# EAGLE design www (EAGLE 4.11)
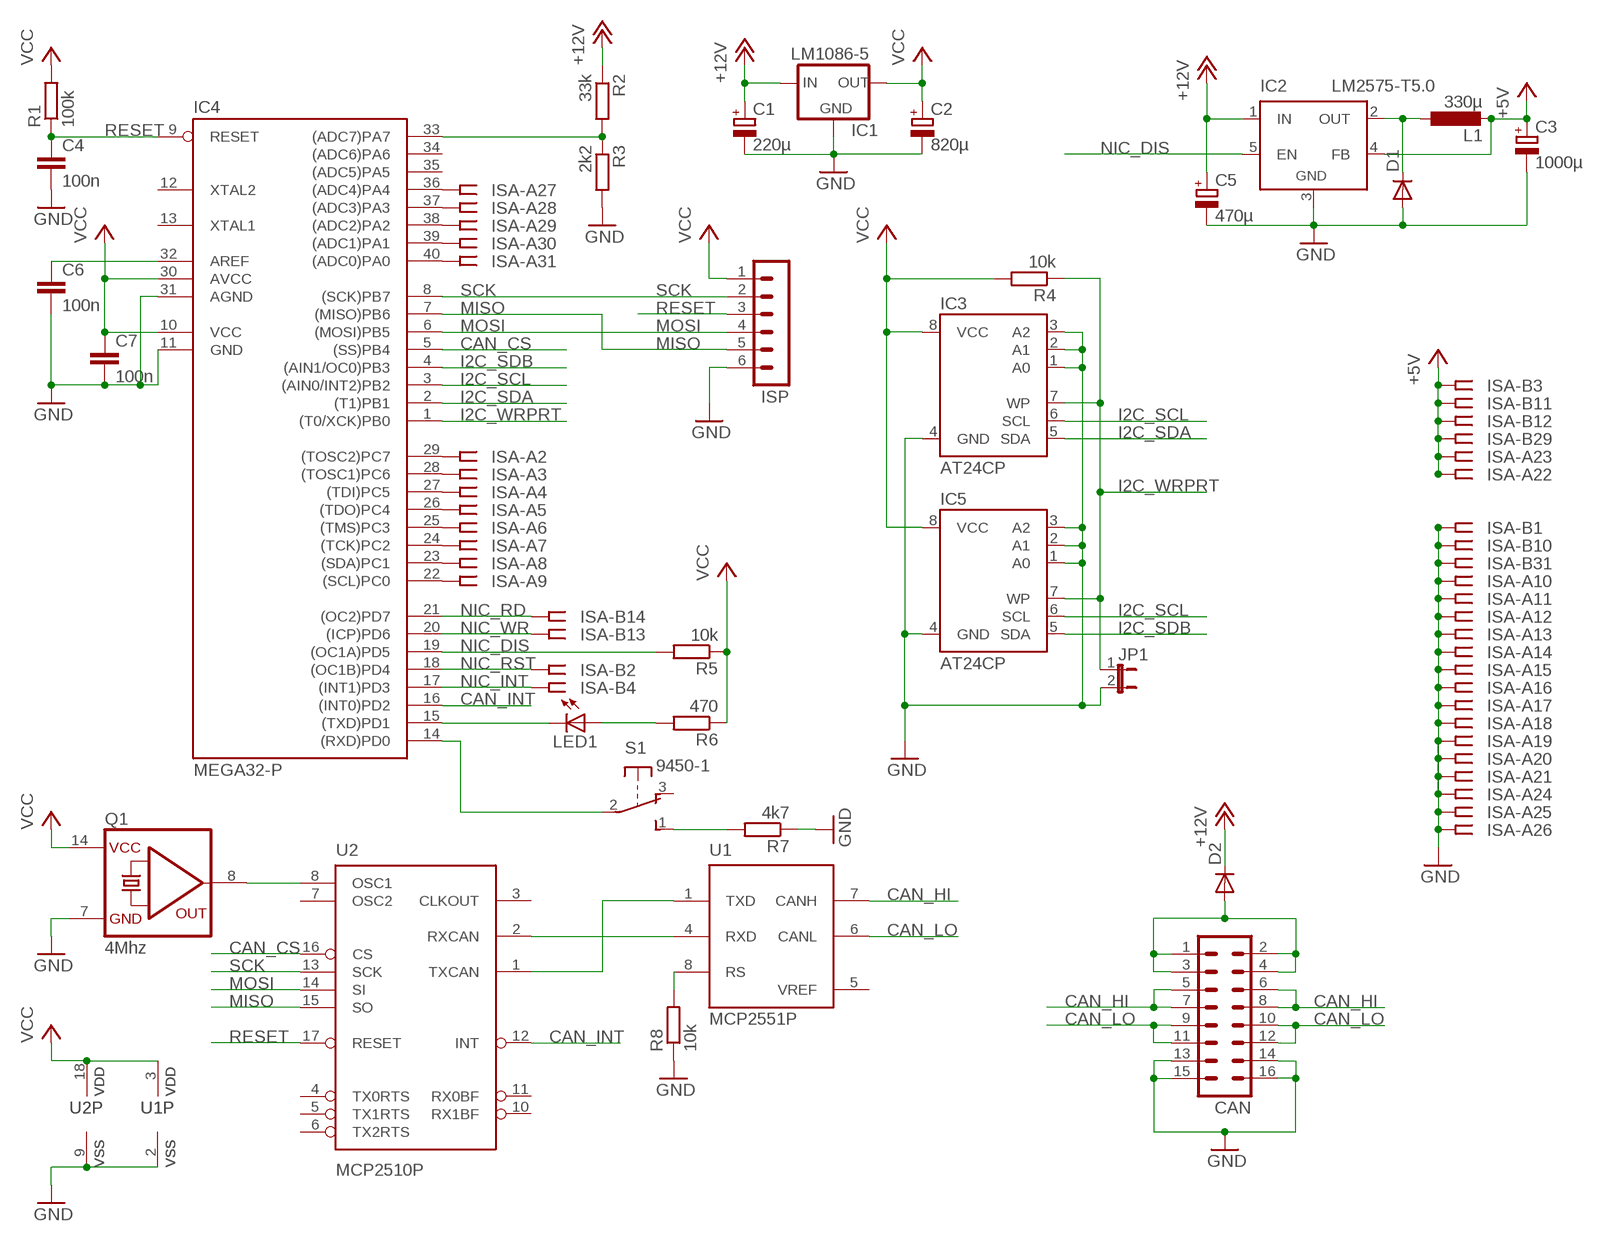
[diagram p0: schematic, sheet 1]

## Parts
C1  220µ  CPOL-EUE7.5-16  [E7,5-16]
C2  820µ  CPOL-EUE5-8.5  [E5-8,5]
C3  1000µ  CPOL-EUE7.5-16  [E7,5-16]
C4  100n  C5/3  [C5B3]
C5  470µ  CPOL-EUE5-8.5  [E5-8,5]
C6  100n  C5/3  [C5B3]
C7  100n  C2,5-3  [C2.5-3]
CAN  MA08-2  [MA08-2]
D1  DIODE-DO201-15  [DO201-15]
D2  DIODE-DO201-15  [DO201-15]
IC1  LM1086-5  [TO220S]
IC2  LM2575-T5.0  LM2575TV  [TO220-51]
IC3  AT24CP  [DIL08]
IC4  MEGA32-P  [DIL40]
IC5  AT24CP  [DIL08]
ISA  ISA-SLOT-SHORT  [ISA-SHORT]
ISP  MA06-1  [MA06-1]
JP1  JP1E  [JP1]
L1  330µ  L-FASTRONL-F/R12  [0307/30]
LED1  LED5MM  [LED5MM]
Q1  4Mhz  QG5860  [DIL14S]
R1  100k  R-EU_0207/2V  [0207/2V]
R2  33k  R-EU_0207/10  [0207/10]
R3  2k2  R-EU_0207/2V  [0207/2V]
R4  10k  R-EU_0207/7  [0207/7]
R5  10k  R-EU_0207/5V  [0207/5V]
R6  470  R-EU_0207/7  [0207/7]
R7  4k7  R-EU_0207/7  [0207/7]
R8  10k  R-EU_0207/7  [0207/7]
S1  9450-1  [9450-1]
U1  MCP2551P  [DIL8]
U2  MCP2510P  [DIL18]

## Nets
+5V: C3.+ IC2.4(FB) ISA.A22 ISA.A23 ISA.B3 ISA.B11 ISA.B12 ISA.B29 L1.2
+12V: C1.+ C5.+ D2.C IC1.3(IN) IC2.1(IN) R2.1
CAN_CS: IC4.5((SS)PB4) U2.16(CS)
CAN_HI: CAN.5 CAN.6 CAN.7 CAN.8 U1.7(CANH)
CAN_INT: IC4.16((INT0)PD2) U2.12(INT)
CAN_LO: CAN.9 CAN.10 CAN.11 CAN.12 U1.6(CANL)
GND: C1.- C2.- C3.- C4.2 C5.- C6.2 C7.2 CAN.13 CAN.14 CAN.15 CAN.16 D1.A IC1.1(GND) IC2.3(GND) IC3.1(A0) IC3.2(A1) IC3.3(A2) IC3.4(GND) IC4.11(GND) IC4.31(AGND) IC5.1(A0) IC5.2(A1) IC5.3(A2) IC5.4(GND) ISA.A10 ISA.A11 ISA.A12 ISA.A13 ISA.A14 ISA.A15 ISA.A16 ISA.A17 ISA.A18 ISA.A19 ISA.A20 ISA.A21 ISA.A24 ISA.A25 ISA.A26 ISA.B1 ISA.B10 ISA.B31 ISP.6 JP1.2 Q1.7(GND) R3.2 R7.1 R8.1 U1.2(VSS) U2.9(VSS)
I2C_SCL: IC3.6(SCL) IC4.3((AIN0/INT2)PB2) IC5.6(SCL)
I2C_SDA: IC3.5(SDA) IC4.2((T1)PB1)
I2C_SDB: IC4.4((AIN1/OC0)PB3) IC5.5(SDA)
I2C_WRPRT: IC3.7(WP) IC4.1((T0/XCK)PB0) IC5.7(WP) JP1.1 R4.1
MISO: IC4.7((MISO)PB6) ISP.5 U2.15(SO)
MOSI: IC4.6((MOSI)PB5) ISP.4 U2.14(SI)
N$1: Q1.8(OUT) U2.8(OSC1)
N$2: IC4.15((TXD)PD1) LED1.K(C)
N$3: D1.C IC2.2(OUT) L1.1
N$4: IC4.29((TOSC2)PC7) ISA.A2
N$5: IC4.28((TOSC1)PC6) ISA.A3
N$6: IC4.27((TDI)PC5) ISA.A4
N$7: IC4.26((TDO)PC4) ISA.A5
N$8: IC4.25((TMS)PC3) ISA.A6
N$9: IC4.24((TCK)PC2) ISA.A7
N$10: IC4.23((SDA)PC1) ISA.A8
N$11: IC4.22((SCL)PC0) ISA.A9
N$12: IC4.36((ADC4)PA4) ISA.A27
N$13: IC4.37((ADC3)PA3) ISA.A28
N$14: IC4.38((ADC2)PA2) ISA.A29
N$15: IC4.39((ADC1)PA1) ISA.A30
N$16: IC4.40((ADC0)PA0) ISA.A31
N$17: IC4.14((RXD)PD0) S1.2(P)
N$18: LED1.A R6.2
N$19: R7.2 S1.1(S)
N$20: IC4.33((ADC7)PA7) R2.2 R3.1
N$23: C6.1 IC4.32(AREF)
N$24: U1.4(RXD) U2.2(RXCAN)
N$25: U1.1(TXD) U2.1(TXCAN)
N$26: R8.2 U1.8(RS)
N$27: CAN.1 CAN.2 CAN.3 CAN.4 D2.A
NIC_DIS: IC2.5(EN) IC4.19((OC1A)PD5) R5.2
NIC_INT: IC4.17((INT1)PD3) ISA.B4
NIC_RD: IC4.21((OC2)PD7) ISA.B14
NIC_RST: IC4.18((OC1B)PD4) ISA.B2
NIC_WR: IC4.20((ICP)PD6) ISA.B13
RESET: C4.1 IC4.9(RESET) ISP.3 R1.1 U2.17(RESET)
SCK: IC4.8((SCK)PB7) ISP.2 U2.13(SCK)
VCC: C2.+ C7.1 IC1.2(OUT) IC3.8(VCC) IC4.10(VCC) IC4.30(AVCC) IC5.8(VCC) ISP.1 Q1.14(VCC) R1.2 R4.2 R5.1 R6.1 U1.3(VDD) U2.18(VDD)
Unconnected: IC4.12(XTAL2) IC4.13(XTAL1) IC4.34((ADC6)PA6) IC4.35((ADC5)PA5) ISA.A1 ISA.B5 ISA.B6 ISA.B7 ISA.B8 ISA.B9 ISA.B15 ISA.B16 ISA.B17 ISA.B18 ISA.B19 ISA.B20 ISA.B21 ISA.B22 ISA.B23 ISA.B24 ISA.B25 ISA.B26 ISA.B27 ISA.B28 ISA.B30 S1.3(O) U2.3(CLKOUT) U2.4(TX0RTS) U2.5(TX1RTS) U2.6(TX2RTS) U2.7(OSC2) U2.10(RX1BF) U2.11(RX0BF)

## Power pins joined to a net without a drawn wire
VREF: U1.5(VREF)

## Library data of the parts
C1-C3 C5 = rcl:CPOL-EU: POLARIZED CAPACITOR, European symbol
C4 C6 C7 = capacitor-wima:C: CAPACITOR
CAN = con-lstb:MA08-2: PIN HEADER
D1 D2 = diode:DIODE-: DIODE
IC1 = lm108x:LM1086-5
IC2 = lib:LM2575T: STEP-DOWN VOLTAGE REGULATOR
IC3 IC5 = atmel:AT24C*: 2-wire serial EEPROM
IC4 = avr2:MEGA32-P: MICROCONTROLLER 32 Kbytes FLASH 2 Kbytes SRAM 1 Kbytes EEPROM USART 8-channel 10 bit ADC
ISA = lib:ISA-SLOT-SHORT: ISA SLOT
ISP = con-lstb:MA06-1: PIN HEADER
JP1 = jumper:JP1E: JUMPER
L1 = lib:L-FASTRON: INDUCTOR, European symbol
LED1 = led:LED: LED
Q1 = crystal:QG5860: CRYSTAL RESONATOR
R1-R8 = rcl:R-EU_: RESISTOR, European symbol
S1 = switch-misc:9450-1: MARQUARDT SWITCH
U1 = microchip_can:MCP2551: High Speed CAN tranceiver
U2 = microchip_can:MCP2510

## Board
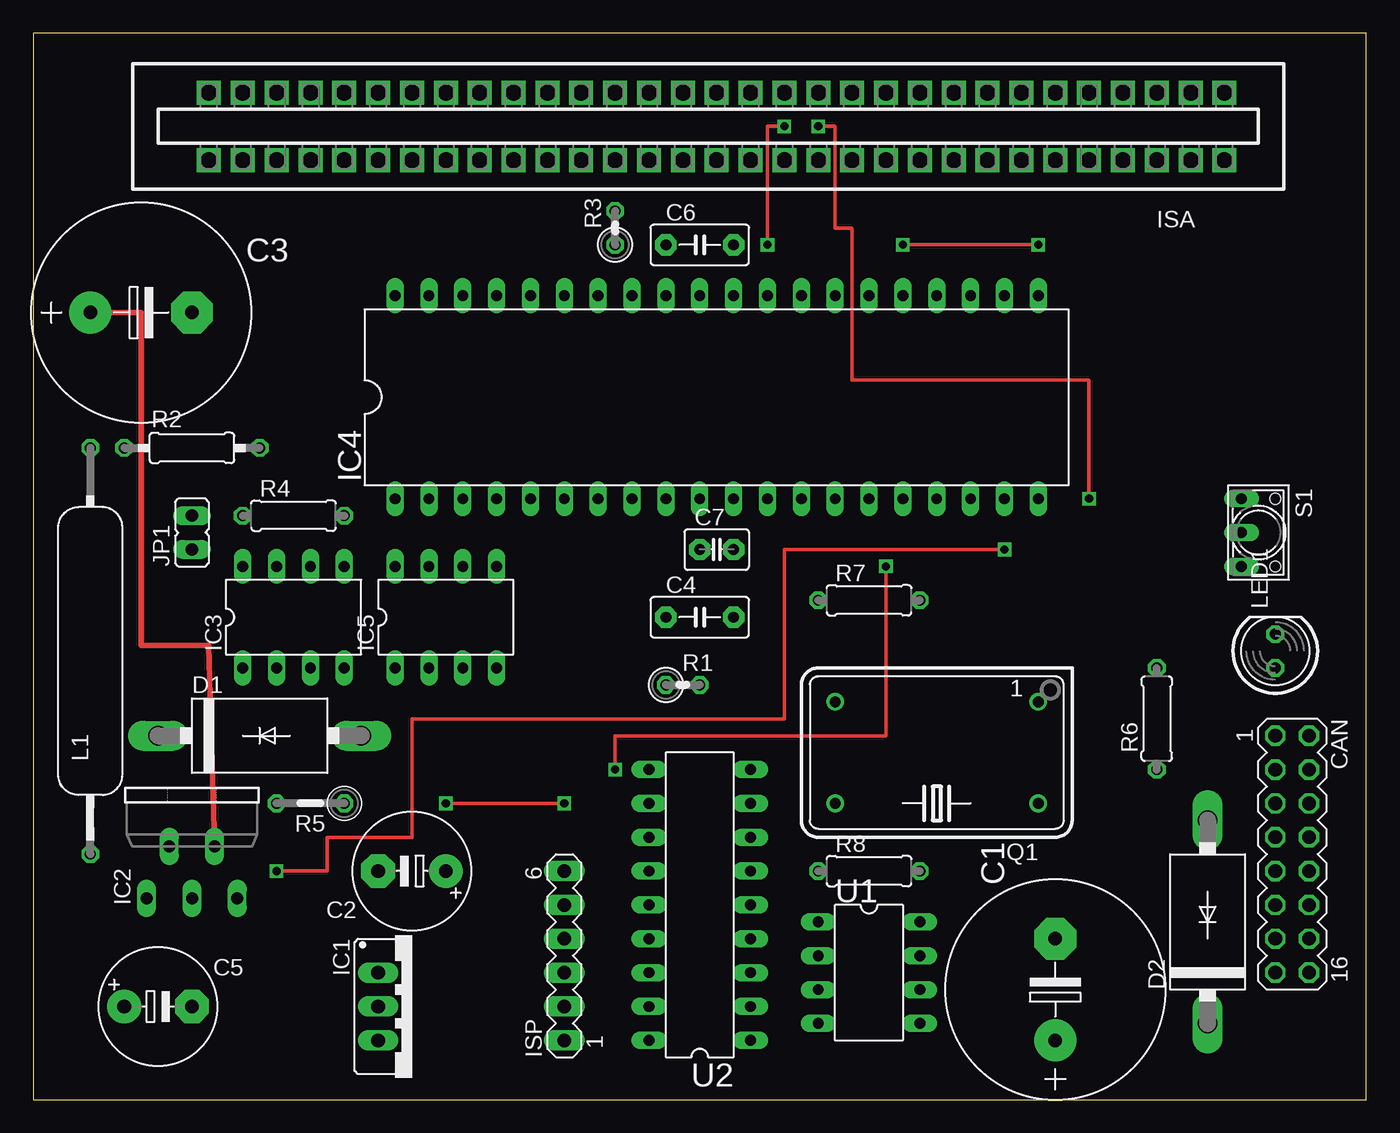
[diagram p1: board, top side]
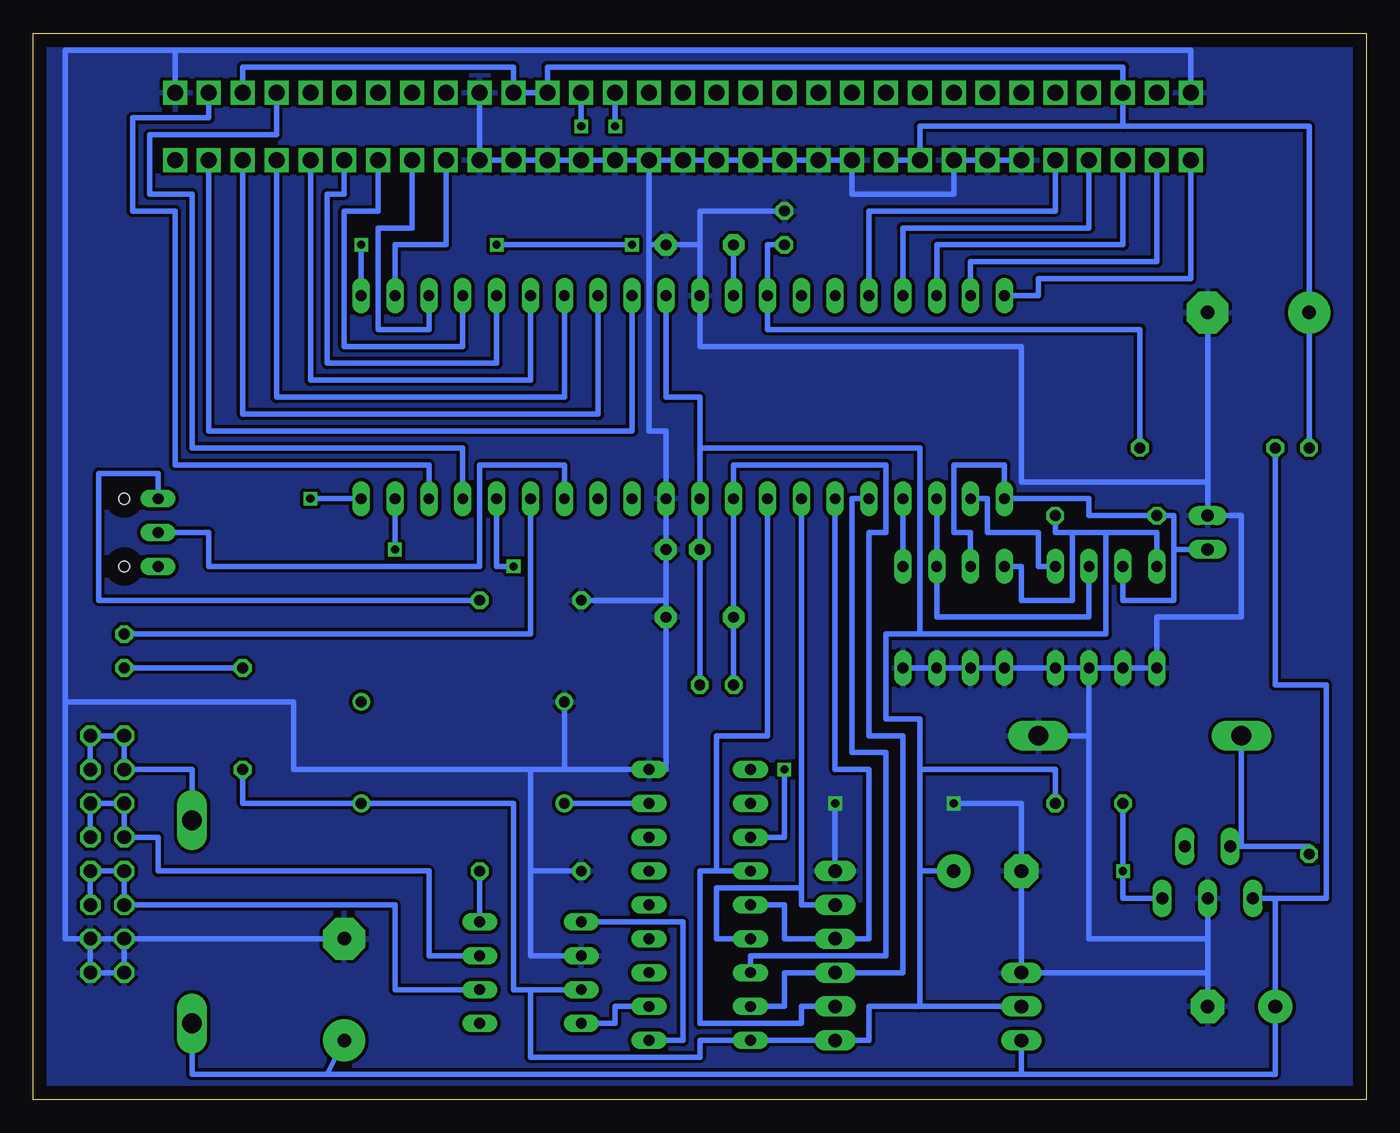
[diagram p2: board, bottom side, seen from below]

Size 100 x 80 mm. Coordinates in mm from the lower left corner, seen from the top.
Outline: 0,0 100,0 100,80 0,80 0,0
Copper layers (1*16): Top 0.035mm / dielectric 1.5mm / Bottom 0.035mm
Design rules "default": minimum track width 10mil, minimum drill 24mil, track to track 8mil, track to pad 8mil, pad to pad 8mil, via to via 8mil, smd to smd 8mil, copper to edge 40mil, drill to drill 8mil, minimum pad ring 10mil, minimum via ring 8mil, stop-mask expansion 4mil, vias tented up to drill 0mil, thermal gap 10mil

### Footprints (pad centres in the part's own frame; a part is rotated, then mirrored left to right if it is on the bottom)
E7,5-16 = drill 1.016 pad 3.15 round: + -3.81,0 | drill 1.016 pad 3.15 octagon: - 3.81,0
E5-8,5 = drill 1.016 pad 2.54 round: + -2.54,0 | drill 1.016 pad 2.54 octagon: - 2.54,0
C5B3 = drill 0.813 pad 1.6 octagon: 1 -2.54,0; 2 2.54,0
C2.5-3 = drill 0.813 pad 1.6 octagon: 1 -1.27,0; 2 1.27,0
MA08-2 = drill 1.016 octagon: 1 -8.89,-1.27; 2 -8.89,1.27; 3 -6.35,-1.27; 4 -6.35,1.27; 5 -3.81,-1.27; 6 -3.81,1.27; 7 -1.27,-1.27; 8 -1.27,1.27; 9 1.27,-1.27; 10 1.27,1.27; 11 3.81,-1.27; 12 3.81,1.27; 13 6.35,-1.27; 14 6.35,1.27; 15 8.89,-1.27; 16 8.89,1.27
DO201-15 = drill 1.499 long: A 7.62,0; C -7.62,0
TO220S = drill 1.016 long: 1 -2.54,-2.54; 2 0,-2.54; 3 2.54,-2.54
TO220-51 = drill 0.9 long: 1 -3.4,-8.4; 2 -1.7,-4.5; 3 0,-8.4; 4 1.7,-4.5; 5 3.4,-8.4
DIL08 = drill 0.813 long: 1 -3.81,-3.81; 2 -1.27,-3.81; 3 1.27,-3.81; 4 3.81,-3.81; 5 3.81,3.81; 6 1.27,3.81; 7 -1.27,3.81; 8 -3.81,3.81
DIL40 = drill 0.813 long: 1 -24.13,-7.62; 2 -21.59,-7.62; 3 -19.05,-7.62; 4 -16.51,-7.62; 5 -13.97,-7.62; 6 -11.43,-7.62; 7 -8.89,-7.62; 8 -6.35,-7.62; 9 -3.81,-7.62; 10 -1.27,-7.62; 11 1.27,-7.62; 12 3.81,-7.62; 13 6.35,-7.62; 14 8.89,-7.62; 15 11.43,-7.62; 16 13.97,-7.62; 17 16.51,-7.62; 18 19.05,-7.62; 19 21.59,-7.62; 20 24.13,-7.62; 21 24.13,7.62; 22 21.59,7.62; 23 19.05,7.62; 24 16.51,7.62; 25 13.97,7.62; 26 11.43,7.62; 27 8.89,7.62; 28 6.35,7.62; 29 3.81,7.62; 30 1.27,7.62; 31 -1.27,7.62; 32 -3.81,7.62; 33 -6.35,7.62; 34 -8.89,7.62; 35 -11.43,7.62; 36 -13.97,7.62; 37 -16.51,7.62; 38 -19.05,7.62; 39 -21.59,7.62; 40 -24.13,7.62
ISA-SHORT = drill 1.2 pad 1.778 square: A1 81.28,-2.54; A2 78.74,-2.54; A3 76.2,-2.54; A4 73.66,-2.54; A5 71.12,-2.54; A6 68.58,-2.54; A7 66.04,-2.54; A8 63.5,-2.54; A9 60.96,-2.54; A10 58.42,-2.54; A11 55.88,-2.54; A12 53.34,-2.54; A13 50.8,-2.54; A14 48.26,-2.54; A15 45.72,-2.54; A16 43.18,-2.54; A17 40.64,-2.54; A18 38.1,-2.54; A19 35.56,-2.54; A20 33.02,-2.54; A21 30.48,-2.54; A22 27.94,-2.54; A23 25.4,-2.54; A24 22.86,-2.54; A25 20.32,-2.54; A26 17.78,-2.54; A27 15.24,-2.54; A28 12.7,-2.54; A29 10.16,-2.54; A30 7.62,-2.54; A31 5.08,-2.54; B1 81.28,2.54; B2 78.74,2.54; B3 76.2,2.54; B4 73.66,2.54; B5 71.12,2.54; B6 68.58,2.54; B7 66.04,2.54; B8 63.5,2.54; B9 60.96,2.54; B10 58.42,2.54; B11 55.88,2.54; B12 53.34,2.54; B13 50.8,2.54; B14 48.26,2.54; B15 45.72,2.54; B16 43.18,2.54; B17 40.64,2.54; B18 38.1,2.54; B19 35.56,2.54; B20 33.02,2.54; B21 30.48,2.54; B22 27.94,2.54; B23 25.4,2.54; B24 22.86,2.54; B25 20.32,2.54; B26 17.78,2.54; B27 15.24,2.54; B28 12.7,2.54; B29 10.16,2.54; B30 7.62,2.54; B31 5.08,2.54
MA06-1 = drill 1.016 long: 1 -6.35,0; 2 -3.81,0; 3 -1.27,0; 4 1.27,0; 5 3.81,0; 6 6.35,0
JP1 = drill 0.914 long: 1 0,-1.27; 2 0,1.27
0307/30 = drill 0.813 octagon: 1 -7.62,0; 2 22.86,0
LED5MM = drill 0.813 octagon: A -1.27,0; K 1.27,0
DIL14S = drill 0.813 round: 1 -7.62,-3.81; 7 7.62,-3.81; 8 7.62,3.81; 14 -7.62,3.81
0207/2V = drill 0.813 octagon: 1 -1.27,0; 2 1.27,0
0207/10 = drill 0.813 octagon: 1 -5.08,0; 2 5.08,0
0207/7 = drill 0.813 octagon: 1 -3.81,0; 2 3.81,0
0207/5V = drill 0.813 octagon: 1 -2.54,0; 2 2.54,0
9450-1 = drill 0.813 long: 1 -2.54,-1.27; 2 0,-1.27; 3 2.54,-1.27 | hole 0.813: 2.54,1.27; -2.54,1.27
DIL8 = drill 0.813 long: 1 -3.81,-3.81; 2 -1.27,-3.81; 3 1.27,-3.81; 4 3.81,-3.81; 5 3.81,3.81; 6 1.27,3.81; 7 -1.27,3.81; 8 -3.81,3.81
DIL18 = drill 0.813 long: 1 -10.16,-3.81; 2 -7.62,-3.81; 3 -5.08,-3.81; 4 -2.54,-3.81; 5 0,-3.81; 6 2.54,-3.81; 7 5.08,-3.81; 8 7.62,-3.81; 9 10.16,-3.81; 10 10.16,3.81; 11 7.62,3.81; 12 5.08,3.81; 13 2.54,3.81; 14 0,3.81; 15 -2.54,3.81; 16 -5.08,3.81; 17 -7.62,3.81; 18 -10.16,3.81

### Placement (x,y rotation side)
C1  76.67,8.25 90 top
C2  28.41,17.14 180 top
C3  8.09,59.05 0 top
C4  50,36.19 0 top
C5  9.36,6.98 0 top
C6  50,64.13 0 top
C7  51.27,41.27 0 top
CAN  94.45,18.41 270 top
D1  16.98,27.3 0 top
D2  88.1,13.33 90 top
IC1  28.41,6.98 270 top
IC2  11.9,23.49 0 top
IC3  19.52,36.19 0 top
IC4  51.27,52.7 0 top
IC5  30.95,36.19 0 top
ISA  8.09,73.02 0 top
ISP  39.84,10.79 90 top
JP1  11.9,42.54 0 top
L1  4.28,26.03 90 top
LED1  93.18,33.65 90 top
Q1  67.78,26.03 180 top
R1  48.73,31.11 0 top
R2  11.9,48.89 0 top
R3  43.65,65.4 90 top
R4  19.52,43.81 0 top
R5  20.79,22.22 180 top
R6  84.29,28.57 90 top
R7  62.7,37.46 0 top
R8  62.7,17.14 0 top
S1  91.91,42.54 270 top
U1  62.7,9.52 270 top
U2  50,14.6 90 top

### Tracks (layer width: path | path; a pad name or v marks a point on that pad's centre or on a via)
+5V
  Top 0.406: IC2.4 13.17,34.08 8.09,34.08 8.09,59.05 C3.+
  Bottom 0.406: ISA.A22 ISA.A23 33.49,73.02 18.25,73.02 | 18.25,73.02 ISA.B29 18.25,77.46 61.43,77.46 ISA.B12 ISA.B11 63.97,77.46 84.29,77.46 ISA.B3 | L1.2 C3.+ 4.28,73.02 18.25,73.02
+12V
  Bottom 0.406: 6.82,15.09 3.01,15.09 3.01,31.11 6.82,31.11 R2.1 | 6.82,15.09 4.28,15.09 | 6.82,15.09 IC2.1 | 25.87,1.9 6.82,1.9 C5.+ 6.82,15.09 | 25.87,1.9 IC1.3 | 25.87,1.9 77.94,1.9 | 77.94,1.9 88.1,1.9 D2.C | 77.94,1.9 C1.+
CAN_CS
  Bottom 0.406: U2.16 46.19,10.79 36.03,10.79 36.03,26.03 38.57,26.03 38.57,45.08 IC4.5
CAN_HI
  Bottom 0.406: CAN.8 CAN.6 CAN.5 CAN.7 90.64,19.68 90.64,17.14 70.32,17.14 70.32,10.79 U1.7
CAN_INT  (via drill 0.61)
  Top 0.254: v43.65,24.76 43.65,27.3 63.97,27.3 v63.97,40
  Bottom 0.406: U2.12 43.65,19.68 v43.65,24.76 | v63.97,40 65.24,40 IC4.16
CAN_LO
  Bottom 0.406: U1.6 72.86,8.25 72.86,14.6 CAN.11 CAN.9 CAN.10 CAN.12
GND  (via drill 0.61)
  Top 0.254: v30.95,22.22 v39.84,22.22
  Bottom 0.406: U1.2 62.7,10.79 62.7,17.14 | 62.7,24.76 62.7,17.14 | 60.16,24.76 62.7,24.76 | 60.16,24.76 U2.9 52.54,24.76 C4.2 52.54,37.46 | 60.16,24.76 Q1.7 | IC3.3 IC3.4 | IC3.3 IC3.2 IC3.1 | IC3.3 IC3.1 | IC3.3 IC5.1 IC5.2 IC5.3 IC5.4 | 53.81,64.13 C6.2 50,64.13 | 53.81,64.13 53.81,50.16 52.54,50.16 IC4.11 C7.2 52.54,37.46 | ISA.A15 ISA.A14 ISA.A13 ISA.A12 ISA.A11 ISA.A10 ISA.B10 | ISA.A15 ISA.A16 ISA.A17 ISA.A18 ISA.A19 ISA.A20 ISA.A21 38.57,67.94 30.95,67.94 ISA.A24 ISA.A25 ISA.A26 | 53.81,64.13 ISA.A15 | 11.9,46.35 C3.- | 11.9,46.35 25.87,46.35 25.87,56.51 50,56.51 IC4.31 50,64.13 | ISA.B31 13.17,78.73 89.37,78.73 | R3.2 50,66.67 50,64.13 | 11.9,12.06 IC2.3 | 11.9,12.06 20.79,12.06 20.79,27.3 | 20.79,27.3 IC3.3 | 20.79,27.3 D1.A | C5.- 11.9,9.52 | 11.9,9.52 11.9,12.06 | 11.9,9.52 IC1.1 C2.- 25.87,22.22 v30.95,22.22 | v39.84,22.22 ISP.6 | 62.7,17.14 R8.1 | 11.9,46.35 JP1.2 9.36,43.81 9.36,36.19 15.71,36.19 IC3.1 | CAN.14 CAN.13 | CAN.14 CAN.13 | CAN.14 97.62,12.06 97.62,29.84 | 97.62,29.84 80.48,29.84 80.48,24.76 62.7,24.76 | CAN.13 C1.- | CAN.13 CAN.15 CAN.16 CAN.14 | 89.37,78.73 97.62,78.73 97.62,29.84 | 89.37,78.73 ISA.B1 | 52.54,37.46 R7.1
  pour Bottom (isolate 0.254): -0.8,80.64 100.8,80.64 100.8,-0.64 -0.8,-0.64
I2C_SCL
  Bottom 0.406: IC3.6 20.79,36.19 32.22,36.19 IC5.6 IC4.3
I2C_SDA
  Bottom 0.406: IC3.5 24.6,40 24.6,42.54 28.41,42.54 28.41,45.08 IC4.2
I2C_SDB
  Bottom 0.406: IC5.5 IC4.4
I2C_WRPRT
  Bottom 0.406: IC3.7 18.25,37.46 14.44,37.46 14.44,41.27 | 14.44,41.27 14.44,43.81 R4.1 20.79,43.81 20.79,45.08 IC4.1 27.14,47.62 30.95,47.62 30.95,42.54 29.68,42.54 IC5.7 | 14.44,41.27 JP1.1
MISO
  Bottom 0.406: U2.15 48.73,12.06 48.73,15.87 42.38,15.87 | 42.38,15.87 42.38,14.6 ISP.5 | 42.38,15.87 IC4.7
MOSI
  Bottom 0.406: U2.14 43.65,14.6 43.65,12.06 ISP.4 37.3,12.06 37.3,24.76 39.84,24.76 IC4.6
N$1
  Bottom 0.406: U2.8 Q1.8
N$2
  Bottom 0.406: LED1.K 62.7,34.92 IC4.15
N$3
  Bottom 0.406: D1.C 9.36,18.99 IC2.2 4.28,18.99 L1.1
N$4
  Bottom 0.406: IC4.29 55.08,50.16 86.83,50.16 ISA.A2
N$5
  Bottom 0.406: IC4.28 57.62,51.43 84.29,51.43 ISA.A3
N$6
  Bottom 0.406: IC4.27 60.16,52.7 81.75,52.7 ISA.A4
N$7
  Bottom 0.406: ISA.A5 79.21,53.97 62.7,53.97 IC4.26
N$8
  Bottom 0.406: ISA.A6 76.67,67.94 77.94,67.94 77.94,55.24 65.24,55.24 IC4.25
N$9
  Bottom 0.406: IC4.24 67.78,56.51 76.67,56.51 76.67,66.67 74.13,66.67 ISA.A7
N$10
  Bottom 0.406: ISA.A8 71.59,65.4 74.13,65.4 74.13,57.78 70.32,57.78 IC4.23
N$11
  Bottom 0.406: IC4.22 72.86,64.13 69.05,64.13 ISA.A9
N$12
  Bottom 0.406: IC4.36 37.3,66.67 23.33,66.67 ISA.A27
N$13
  Bottom 0.406: IC4.37 34.76,65.4 20.79,65.4 ISA.A28
N$14
  Bottom 0.406: ISA.A29 18.25,64.13 32.22,64.13 IC4.38
N$15
  Bottom 0.406: IC4.39 29.68,62.86 15.71,62.86 ISA.A30
N$16
  Bottom 0.406: ISA.A31 13.17,61.59 24.6,61.59 24.6,60.32 IC4.40
N$17
  Bottom 0.406: S1.2 86.83,42.54 86.83,40 66.51,40 66.51,47.62 60.16,47.62 IC4.14
N$18
  Bottom 0.406: R6.2 LED1.A
N$19
  Bottom 0.406: R7.2 95.08,37.46 95.08,46.98 90.64,46.98 S1.1
N$20
  Bottom 0.406: R2.2 16.98,57.78 44.92,57.78 IC4.33 44.92,64.13 R3.1
N$23
  Bottom 0.406: IC4.32 C6.1
N$24
  Bottom 0.406: U2.2 56.35,6.98 56.35,5.71 U1.4
N$25
  Bottom 0.406: U2.1 51.27,4.44 51.27,13.33 U1.1
N$26
  Bottom 0.406: U1.8 R8.2
N$27
  Bottom 0.406: CAN.4 CAN.2 CAN.1 CAN.3 88.1,24.76 D2.A
NIC_DIS  (via drill 0.61)
  Top 0.254: v18.25,17.14 22.06,17.14 22.06,19.68 28.41,19.68 28.41,28.57 56.35,28.57 56.35,41.27 v72.86,41.27
  Bottom 0.406: IC2.5 18.25,15.09 v18.25,17.14 R5.2 | v72.86,41.27 IC4.19
NIC_INT
  Bottom 0.406: ISA.B4 81.75,72.38 91.28,72.38 91.28,67.94 88.1,67.94 88.1,48.89 67.78,48.89 IC4.17
NIC_RD  (via drill 0.61)
  Top 0.254: v56.35,73.02 55.08,73.02 v55.08,64.13 | v65.24,64.13 v75.4,64.13
  Bottom 0.406: v56.35,73.02 ISA.B14 | v55.08,64.13 v65.24,64.13 | v75.4,64.13 IC4.21
NIC_RST
  Bottom 0.406: ISA.B2 86.83,73.66 92.55,73.66 92.55,66.67 89.37,66.67 89.37,47.62 70.32,47.62 IC4.18
NIC_WR  (via drill 0.61)
  Top 0.254: v58.89,73.02 60.16,73.02 60.16,65.4 61.43,65.4 61.43,53.97 79.21,53.97 v79.21,45.08
  Bottom 0.406: v58.89,73.02 ISA.B13 | v79.21,45.08 IC4.20
RESET
  Bottom 0.406: U2.17 43.65,6.98 43.65,9.52 ISP.3 34.76,9.52 34.76,27.3 37.3,27.3 37.3,42.54 36.03,42.54 36.03,47.62 47.46,47.62 IC4.9 C4.1 R1.1
SCK
  Bottom 0.406: ISP.2 42.38,6.98 42.38,5.71 50,5.71 50,17.14 48.73,17.14 | 48.73,17.14 U2.13 | 48.73,17.14 48.73,27.3 44.92,27.3 IC4.8
VCC
  Bottom 0.406: 62.7,8.25 62.7,3.17 50,3.17 50,4.44 U2.18 ISP.1 37.3,4.44 37.3,6.98 33.49,6.98 | 62.7,8.25 U1.3 | 62.7,8.25 63.97,8.25 63.97,22.22 Q1.14 84.29,22.22 R6.1 | IC5.8 25.87,40 25.87,37.46 22.06,37.46 22.06,42.54 | 19.52,42.54 15.71,42.54 IC3.8 | 19.52,42.54 22.06,42.54 | 19.52,42.54 19.52,34.92 33.49,34.92 | R4.2 23.33,42.54 22.06,42.54 | R1.2 C7.1 IC4.10 50,48.89 | 50,48.89 50,52.7 52.54,52.7 IC4.30 | 33.49,34.92 33.49,48.89 50,48.89 | 33.49,6.98 33.49,17.14 | IC1.2 33.49,6.98 | 33.49,17.14 C2.+ | 33.49,17.14 33.49,24.76 | 33.49,24.76 33.49,28.57 36.03,28.57 36.03,34.92 33.49,34.92 | R5.1 23.33,24.76 33.49,24.76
